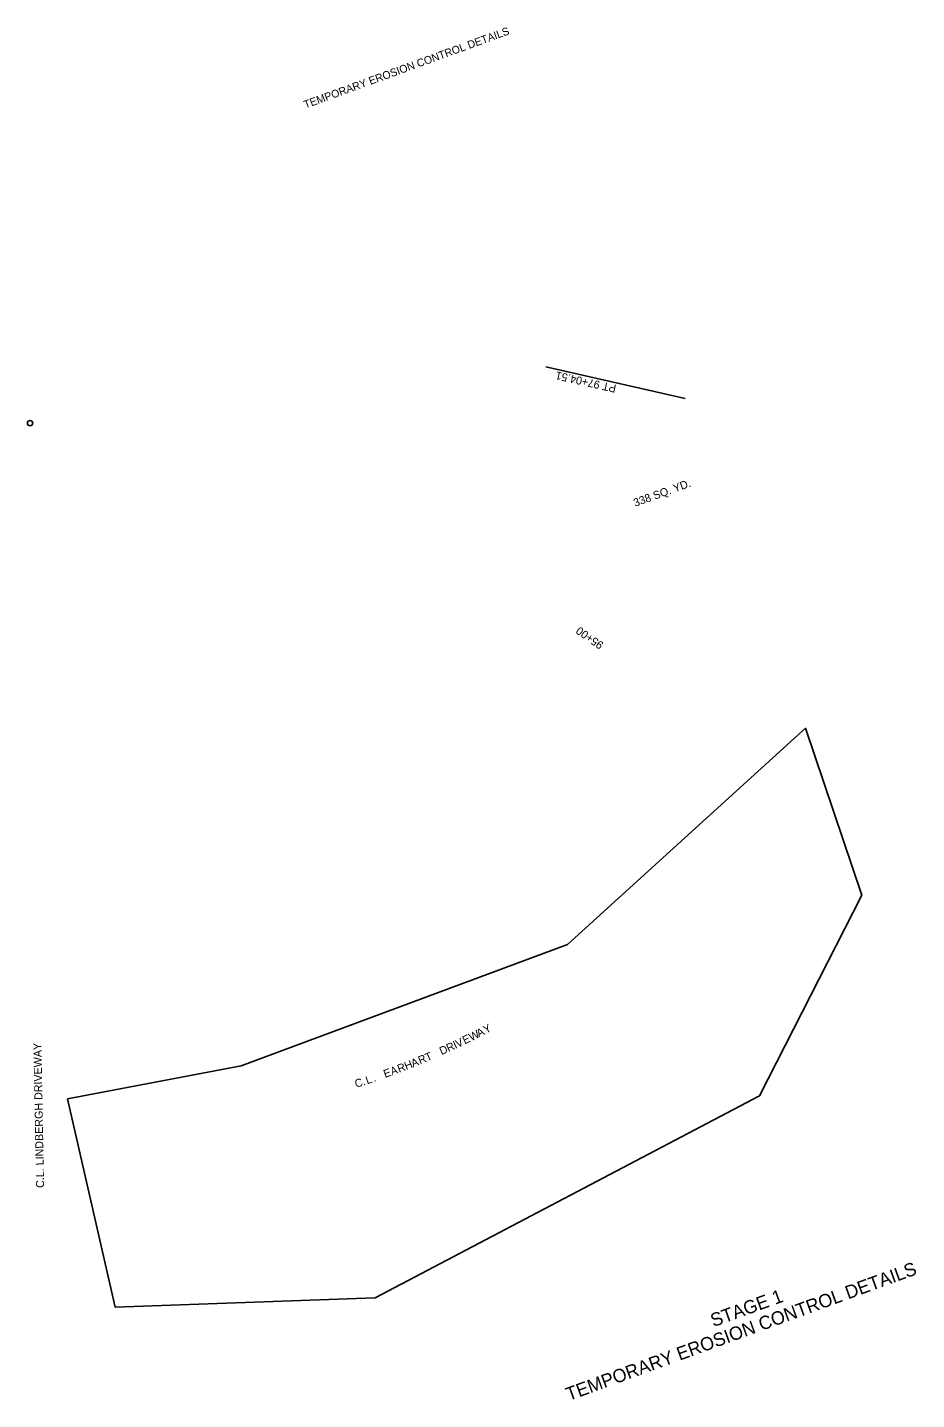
# Model space of a CAD drawing. Extents: x 1710835 to 1712392, y 548501 to 549912.
# Drawn here: x 1711725 to 1712392, y 548883 to 549912 of the extents above; entities that cross this region are included whole.
import ezdxf

# ---------------------------------------------------------------- set-up
doc = ezdxf.new("R2010")
doc.units = 0
for name, color, linetype in [('R_Border', 7, 'Continuous'), ('R_Contours', 7, 'Continuous'), ('R_Horz Alg Annot', 7, 'Continuous'), ('R_MOT', 7, 'Continuous')]:
    doc.layers.add(name, color=color, linetype=linetype)

msp = doc.modelspace()

# ---------------------------------------------------------------- linework, layer by layer
at = {"layer": 'R_Contours'}
msp.add_lwpolyline([(1711754.8, 549108.5), (1711885, 549133.2), (1712129.9, 549224.3), (1712308.3, 549386.5), (1712350.7, 549261.3), (1712273.9, 549110.8), (1711985.5, 548959.3), (1711790.7, 548952.3)], close=True, dxfattribs=at)
at = {"layer": 'R_MOT'}
msp.add_lwpolyline([(1712218, 549633.8), (1712113.7, 549657.5)], dxfattribs=at)
msp.add_circle((1711726.8, 549615.3), 2, dxfattribs=at)

# ---------------------------------------------------------------- texts
at = {"layer": 'R_Border'}
msp.add_text('TEMPORARY EROSION CONTROL DETAILS', height=5.862, rotation=20, dxfattribs=at).set_placement((1711933.3, 549851.2))
at = {"layer": 'R_Horz Alg Annot'}
for s, height, rotation, p in [('338 SQ. YD.', 6, 20, (1712180.6, 549552.5)), ('W', 6, 26.5311, (1712057.7, 549151.7)), ('A', 6, 27.1121, (1712063.4, 549154.6)), ('Y', 6, 27.6419, (1712068.6, 549157.3)), ('C.L. LINDBERGH DRIVEWAY', 6, 91.0787, (1711737.3, 549041.8)), ('R', 6, 24.8223, (1712040.6, 549143.6)), ('I', 6, 25.3349, (1712045.7, 549146)), ('V', 6, 25.5144, (1712047.5, 549146.8)), ('E', 6, 26.0441, (1712052.8, 549149.4)), ('R', 6, 22.7247, (1712019.3, 549134.4)), ('T', 6, 23.2373, (1712024.6, 549136.5)), ('D', 6, 24.3096, (1712035.4, 549141.3)), ('E', 6, 20.1785, (1711993.1, 549124.2)), ('A', 6, 20.6655, (1711998.1, 549126)), ('R', 6, 21.1953, (1712003.6, 549128.1)), ('H', 6, 21.7079, (1712008.9, 549130.1)), ('A', 6, 22.1949, (1712013.9, 549132.1)), ('C', 6, 18.1065, (1711971.4, 549116.8)), ('.', 6, 18.6192, (1711976.8, 549118.5)), ('L', 6, 18.8841, (1711979.6, 549119.4)), ('.', 6, 19.3711, (1711984.7, 549121.2)), ('TEMPORARY EROSION CONTROL DETAILS', 10, 20, (1712130.8, 548881.9)), ('STAGE 1', 10, 20, (1712239.3, 548937.3))]:
    msp.add_text(s, height=height, rotation=rotation, dxfattribs=at).set_placement(p)
at = {"layer": 'R_MOT'}
for s, rotation, p in [('PT 97+04.51', 167.2066, (1712166.8, 549643.9)), ('95+00', 145.2214, (1712157.4, 549450.2))]:
    msp.add_text(s, height=6, rotation=rotation, dxfattribs=at).set_placement(p)

doc.saveas('drawing.dxf')
